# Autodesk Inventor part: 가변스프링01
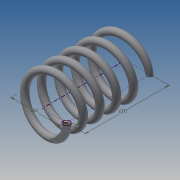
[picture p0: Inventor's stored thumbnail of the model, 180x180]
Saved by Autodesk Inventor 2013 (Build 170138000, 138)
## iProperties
Created: 2014-07
Part Number: 가변스프링01
Material: 일반
Document SubType Name: Modeling
Designer: SEMTLE01_MAIN
Density: 1 g/cm^3
Author: SEMTLE01_MAIN
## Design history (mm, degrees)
sketch "스케치1"
  geometry: L1 (0, 0)-(11, 0); L2 (11, 0)-(11, 25.358); L3 (11, 25.358)-(0, 25.358); L4 (0, 25.358)-(0, 0); C1 r 1.5 at (11, 0)
  constraints: 8 end point, 2 parallel, 1 centre point, 1 coincident, 1 horizontal, 1 perpendicular
  dimensions: "d0" = 3 diameter of C1; "d2" = 22 diameter of L1.end L4; "d3" = 25.35829 distance of L1.end L2.end (derived)
feature "코일1" pitch "d4" = 10; turns "d6" = 5; dims "d5" = 25.35829 (= d3), "d7" = 0, angle "d8" = 90 deg, angle "d9" = 90 deg, "d10" = 0, "d11" = 0
sketch "스케치2"
  geometry: L1 (-12.5, 0)-(-9.5, 0) reference; 1 further point
  constraints: 1 horizontal alignment
extrude "돌출1" cut sketch "스케치2" stored distance "d12" = 10; taper "d13" = 0 deg
node "작업 평면1"
sketch "스케치3"
  geometry: L1 (1.5, 0)-(-1.5, 0) reference; 1 further point
  constraints: 1 horizontal alignment
extrude "돌출2" cut sketch "스케치3" stored distance "d15" = 10; taper "d16" = 0 deg
node "솔리드1"
node "절단 모서리 투영1"
node "절단 모서리 투영2"
other parameters: "d14" = 0
